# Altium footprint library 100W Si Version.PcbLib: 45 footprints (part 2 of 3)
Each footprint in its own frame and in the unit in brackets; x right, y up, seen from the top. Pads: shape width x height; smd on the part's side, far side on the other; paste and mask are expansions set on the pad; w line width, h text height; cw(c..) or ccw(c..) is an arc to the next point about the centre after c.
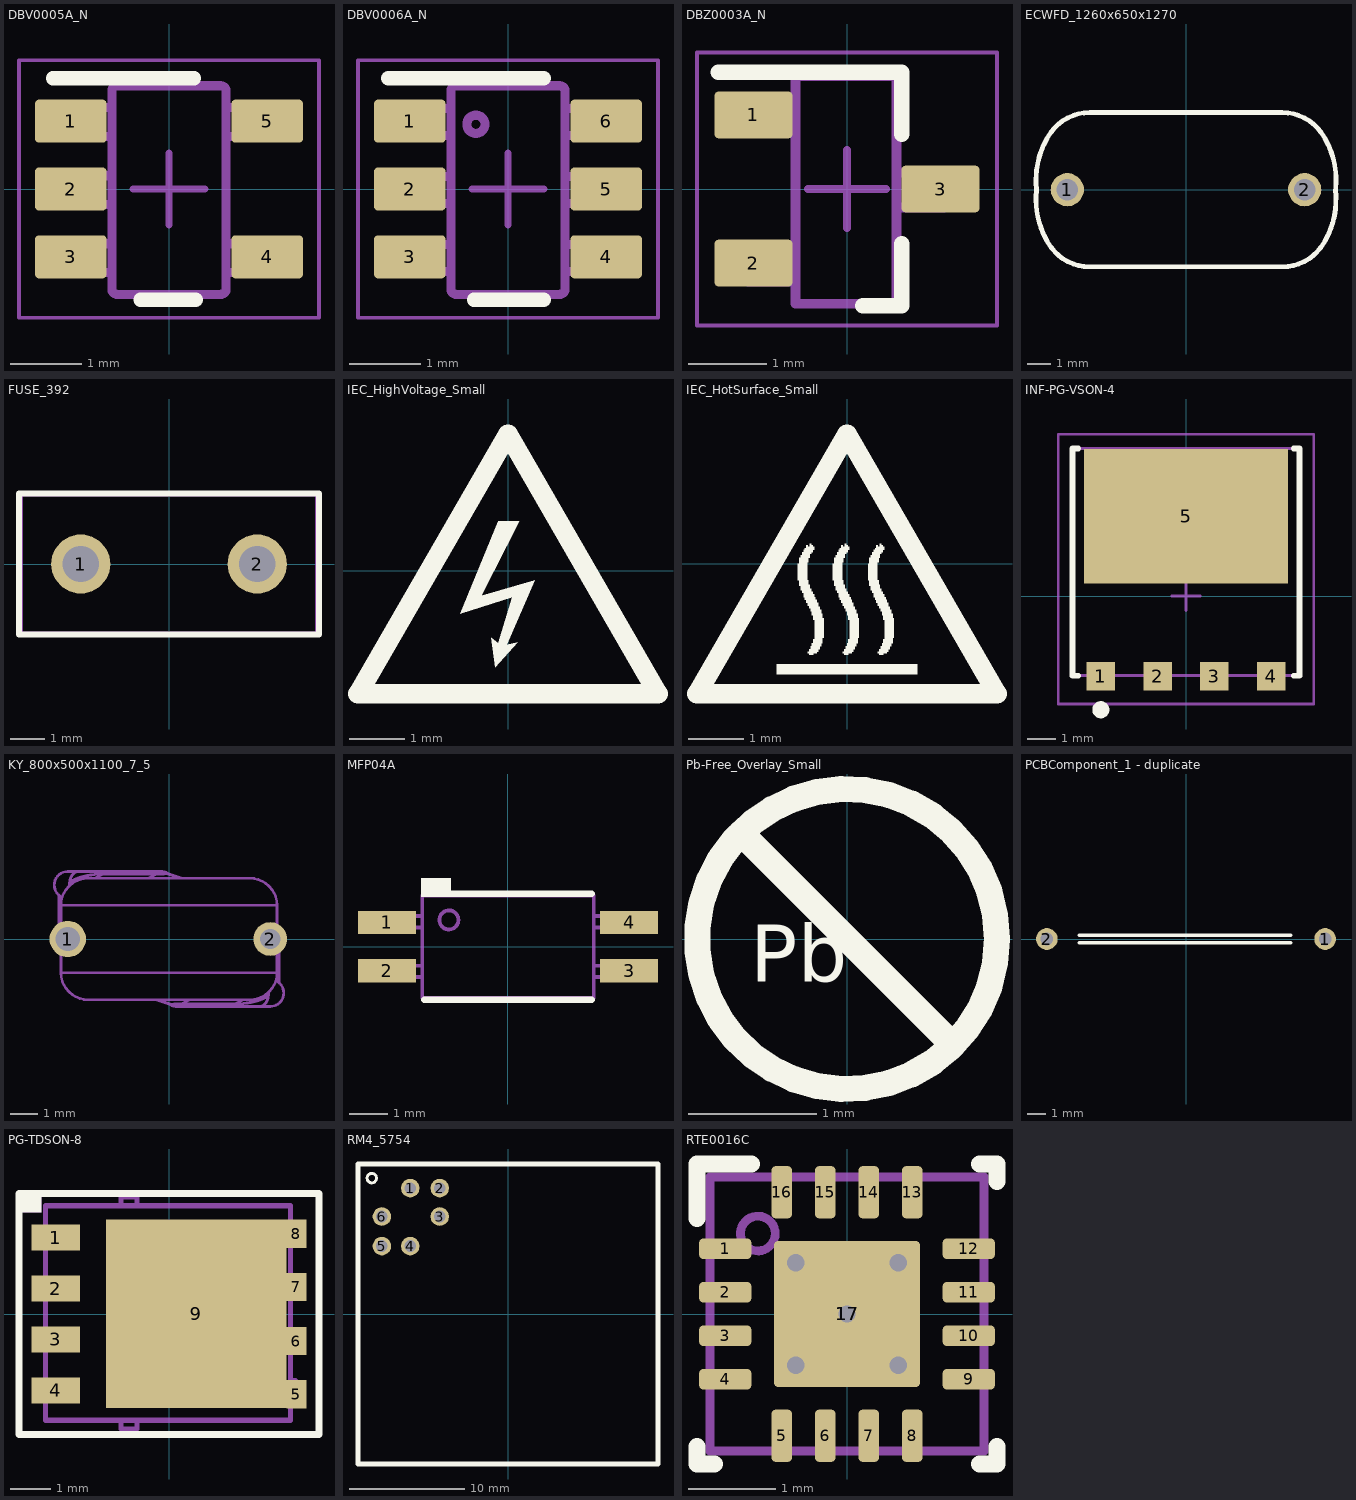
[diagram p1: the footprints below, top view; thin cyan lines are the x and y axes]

## DBV0005A_N [mm] "SOT23, 5-Leads, Body 2.9x1.6mm, Pitch 0.95mm, Lead Span 2.8mm, IPC Medium Density"
height 1.45
pads (5):
  rrect17% 1x0.6 smd: 1(-1.375,0.95) 2(-1.375,0) 3(-1.375,-0.95) 4(1.375,-0.95) 5(1.375,0.95)
Top Overlay:
  lines w0.2: -1.625,1.55 0.35,1.55 ; -0.4,-1.55 0.375,-1.55
Mechanical 5:
  lines w0.127: -0.801,1.371 cw(c-0.725,1.37) -0.725,1.446 ; -0.801,1.37 -0.801,1.371 ; -0.801,1.37 -0.801,-1.399 -0.801,-1.4 ccw(c-0.725,-1.399) -0.725,-1.475 ; -0.725,-1.475 0.723,-1.475 0.724,-1.475 ccw(c0.723,-1.399) 0.799,-1.4 0.799,-1.399 0.799,1.37 ; -0.725,-1.475 -0.725,-1.475 ; -0.725,1.446 -0.725,1.446 ; -0.725,1.446 0.723,1.446 0.724,1.446 cw(c0.723,1.37) 0.799,1.371 ; 0.799,1.37 0.799,1.371 ; -1.423,-1.167 -1.423,-0.767 -1.199,-0.767 -1.105,-0.767 -1.088,-0.767 -0.835,-0.767 -0.801,-0.767 -0.801,-1.167 -0.835,-1.167 -1.088,-1.167 -1.105,-1.167 -1.199,-1.167 -1.423,-1.167 ; -1.423,-0.215 -1.423,0.186 -1.199,0.186 -1.105,0.186 -1.088,0.186 -0.835,0.186 -0.801,0.186 -0.801,-0.215 -0.835,-0.215 -1.088,-0.215 -1.105,-0.215 -1.199,-0.215 -1.423,-0.215 ; -1.423,0.738 -1.423,1.138 -1.199,1.138 -1.105,1.138 -1.088,1.138 -0.835,1.138 -0.801,1.138 -0.801,0.738 -0.835,0.738 -1.088,0.738 -1.105,0.738 -1.199,0.738 -1.423,0.738 ; 0.799,-1.167 0.834,-1.167 1.087,-1.167 1.103,-1.167 1.198,-1.167 1.422,-1.167 1.422,-0.767 1.198,-0.767 1.103,-0.767 1.087,-0.767 0.834,-0.767 0.799,-0.767 0.799,-1.167 ; 0.799,0.738 0.834,0.738 1.087,0.738 1.103,0.738 1.198,0.738 1.422,0.738 1.422,1.138 1.198,1.138 1.103,1.138 1.087,1.138 0.834,1.138 0.799,1.138 0.799,0.738
Mechanical 15:
  lines w0.05: -2.1,-1.8 -2.1,1.8 2.1,1.8 2.1,-1.8 -2.1,-1.8
  lines w0.1: -0.5,0 0.5,0 ; 0,-0.5 0,0.5
3D body "DBV0005A.stp": height 1.09, standoff 0, extent -1.422,-1.46 1.422,1.461

## DBV0006A_N [mm] "SOT23, 6-Leads, Body 2.9x1.6mm, Pitch 0.95mm, Lead Span 2.8mm, IPC Medium Density"
height 1.45
pads (6):
  rrect17% 1x0.6 smd: 1(-1.375,0.95) 2(-1.375,0) 3(-1.375,-0.95) 4(1.375,-0.95) 5(1.375,0) 6(1.375,0.95)
Top Overlay:
  lines w0.2: -1.675,1.55 0.5,1.55 ; -0.475,-1.55 0.5,-1.55
Mechanical 5:
  lines w0.127: 0.724,-1.475 ccw(c0.723,-1.399) 0.8,-1.399 0.8,1.37 ccw(c0.723,1.37) 0.724,1.446 ; 0.723,-1.475 0.724,-1.475 ; 0.723,-1.475 -0.724,-1.475 -0.725,-1.475 cw(c-0.724,-1.399) -0.801,-1.399 -0.801,1.37 cw(c-0.724,1.37) -0.725,1.446 -0.724,1.446 0.723,1.446 ; 0.723,1.446 0.724,1.446 ; -1.423,-1.154 -1.206,-1.154 -1.113,-1.154 -1.081,-1.154 -0.828,-1.154 -0.801,-1.154 -0.801,-0.78 -0.828,-0.78 -1.081,-0.78 -1.113,-0.78 -1.206,-0.78 -1.423,-0.78 -1.423,-1.154 ; -1.423,-0.202 -1.206,-0.202 -1.113,-0.202 -1.081,-0.202 -0.828,-0.202 -0.801,-0.202 -0.801,0.173 -0.828,0.173 -1.081,0.173 -1.113,0.173 -1.206,0.173 -1.423,0.173 -1.423,-0.202 ; -1.423,0.751 -1.206,0.751 -1.113,0.751 -1.081,0.751 -0.828,0.751 -0.801,0.751 -0.801,1.125 -0.828,1.125 -1.081,1.125 -1.113,1.125 -1.206,1.125 -1.423,1.125 -1.423,0.751 ; -0.577,0.906 cw(c-0.45,0.906) -0.323,0.906 cw(c-0.45,0.906) -0.577,0.906 ; 0.8,-1.154 0.827,-1.154 1.08,-1.154 1.112,-1.154 1.205,-1.154 1.422,-1.154 1.422,-0.78 1.205,-0.78 1.112,-0.78 1.08,-0.78 0.827,-0.78 0.8,-0.78 0.8,-1.154 ; 0.8,-0.202 0.827,-0.202 1.08,-0.202 1.112,-0.202 1.205,-0.202 1.422,-0.202 1.422,0.173 1.205,0.173 1.112,0.173 1.08,0.173 0.827,0.173 0.8,0.173 0.8,-0.202 ; 0.8,0.751 0.827,0.751 1.08,0.751 1.112,0.751 1.205,0.751 1.422,0.751 1.422,1.125 1.205,1.125 1.112,1.125 1.08,1.125 0.827,1.125 0.8,1.125 0.8,0.751
  text ".Designator" at -0.075,0.925 h0.76
Mechanical 15:
  lines w0.05: -2.1,-1.8 2.1,-1.8 2.1,1.8 -2.1,1.8 -2.1,-1.8
  lines w0.1: -0.5,0 0.5,0 ; 0,-0.5 0,0.5
3D body "DBV0006A.stp": height 1.12, standoff 0, extent -1.422,-1.46 1.423,1.461

## DBZ0003A_N [mm] "SOT23, 3-Leads, Body 2.9x1.3mm, Pitch 0.95mm, Lead Span 2.4mm, IPC Medium Density"
height 1.12
pads (3):
  rrect17% 1x0.6 smd: 1(-1.2,0.95) 2(-1.2,-0.95) 3(1.2,0)
Top Overlay:
  lines w0.2: -1.651,1.5 0.7,1.5 0.7,0.7 ; 0.2,-1.5 0.7,-1.5 0.7,-0.7
Mechanical 5:
  lines w0.127: -1.27,-1.187 -1.27,-0.743 -1.063,-0.743 -1.005,-0.743 -0.814,-0.743 -0.66,-0.743 -0.66,-1.187 -0.814,-1.187 -1.005,-1.187 -1.063,-1.187 -1.27,-1.187 ; -1.27,0.718 -1.27,1.162 -1.063,1.162 -1.005,1.162 -0.814,1.162 -0.66,1.162 -0.66,0.718 -0.814,0.718 -1.005,0.718 -1.063,0.718 -1.27,0.718 ; -0.66,-1.473 -0.66,1.448 0.635,1.448 0.635,-1.473 -0.66,-1.473 ; 0.635,-0.235 0.789,-0.235 0.98,-0.235 1.037,-0.235 1.245,-0.235 1.245,0.21 1.037,0.21 0.98,0.21 0.789,0.21 0.635,0.21 0.635,-0.235
  text ".Designator" at -0.254,0.889 h0.76
Mechanical 15:
  lines w0.05: -1.925,-1.75 1.925,-1.75 1.925,1.75 -1.925,1.75 -1.925,-1.75
  lines w0.1: -0.5,0 0.5,0 ; 0,-0.5 0,0.5
3D body "DBZ0003A.stp": height 0.98, standoff 0, extent -1.257,-1.46 1.257,1.461

## ECWFD_1260x650x1270 [mm] "TH, 2-Leads, Body 12.6x6.5mm"
height 12.7
pads (2):
  round 1.4 hole 0.9: 1(-5,0) 2(5,0)
Top Overlay:
  lines w0.2: -6.1,-1.625 ccw(c-3.163,-0.595) -5.683,-2.422 -5.681,-2.424 ccw(c-4.058,-1.241) -4.057,-3.25 4.057,-3.25 ccw(c4.058,-1.241) 5.681,-2.424 5.683,-2.422 ccw(c3.163,-0.595) 6.1,-1.625 6.104,-1.614 ccw(c3.053,-0.466) 6.273,-0.975 ccw(c2.734,-0.412) 6.312,-0.609 6.317,-0.282 6.3,0 6.303,0.035 6.318,0.358 ccw(c2.479,0.392) 6.303,0.731 ccw(c2.99,0.448) 6.107,1.606 6.106,1.608 6.106,1.609 6.105,1.611 6.105,1.613 6.104,1.614 6.104,1.616 6.103,1.617 6.102,1.619 6.102,1.62 6.101,1.622 6.1,1.625 ; -6.1,-1.625 -6.101,-1.622 -6.102,-1.62 -6.102,-1.619 -6.103,-1.617 -6.104,-1.616 -6.105,-1.613 -6.106,-1.609 cw(c-2.968,-0.442) -6.309,-0.657 cw(c-2.406,-0.39) -6.317,-0.305 -6.3,0 -6.317,0.29 cw(c-2.345,0.389) -6.312,0.617 cw(c-2.746,0.413) -6.27,0.991 cw(c-3.059,0.468) -6.1,1.625 cw(c-3.163,0.595) -5.683,2.422 -5.681,2.424 cw(c-4.058,1.241) -4.057,3.25 4.057,3.25 cw(c4.058,1.241) 5.681,2.424 5.683,2.422 cw(c3.163,0.595) 6.1,1.625
Mechanical 5:
  lines w0.1: -6.1,-1.625 ccw(c-3.163,-0.595) -5.683,-2.422 -5.681,-2.424 ccw(c-4.058,-1.241) -4.057,-3.25 4.057,-3.25 ccw(c4.058,-1.241) 5.681,-2.424 5.683,-2.422 ccw(c3.163,-0.595) 6.1,-1.625 6.104,-1.614 ccw(c3.053,-0.466) 6.273,-0.975 ccw(c2.734,-0.412) 6.312,-0.609 6.317,-0.282 6.3,0 6.303,0.035 6.318,0.358 ccw(c2.479,0.392) 6.303,0.731 ccw(c2.99,0.448) 6.107,1.606 6.106,1.608 6.106,1.609 6.105,1.611 6.105,1.613 6.104,1.614 6.104,1.616 6.103,1.617 6.102,1.619 6.102,1.62 6.101,1.622 6.1,1.625 ; -6.1,-1.625 -6.101,-1.622 -6.102,-1.62 -6.102,-1.619 -6.103,-1.617 -6.104,-1.616 -6.105,-1.613 -6.106,-1.609 cw(c-2.968,-0.442) -6.309,-0.657 cw(c-2.406,-0.39) -6.317,-0.305 -6.3,0 -6.317,0.29 cw(c-2.345,0.389) -6.312,0.617 cw(c-2.746,0.413) -6.27,0.991 cw(c-3.059,0.468) -6.1,1.625 cw(c-3.163,0.595) -5.683,2.422 -5.681,2.424 cw(c-4.058,1.241) -4.057,3.25 4.057,3.25 cw(c4.058,1.241) 5.681,2.424 5.683,2.422 cw(c3.163,0.595) 6.1,1.625
  text ".Designator" at -2.8,-1 h1.02
3D body "ECWFD_1260x650x1270.stp": height 12.71, standoff -4, extent -6.312,-3.25 6.313,3.25

## FCC_disclaimer [mm]

## FUSE_392 [mm] "LITTELFUSE"
height 8
pads (2):
  round 1.7 hole 1.05: 1(-2.54,0) 2(2.54,0)
Top Overlay:
  lines w0.17: -4.318,-2.032 -4.318,2.032 4.318,2.032 4.318,-2.032 -4.318,-2.032
Mechanical 5:
  lines w0.1: -4.25,-2 -4.25,2 4.25,2 4.25,-2 -4.25,-2
  text ".Designator" at -1.778,-0.508 h1.02
3D body: height 1, standoff -2, extent -2.838,-0.299 -2.24,0.299
3D body: height 1, standoff -2, extent 2.242,-0.299 2.84,0.3
3D body: height 8, standoff 0, extent -4.249,-1.999 4.249,1.999

## IEC_HighVoltage_Small [mm]
Top Overlay:
  region: -0.178,0.889 0.203,0.889 -0.483,-0.457 0.483,-0.178 -0.025,-1.346 0.178,-1.295 -0.229,-1.753 -0.305,-1.219 -0.178,-1.321 0.076,-0.483 -0.864,-0.787
  lines w0.356: -2.718,-2.235 0,2.472 2.718,-2.235 -2.718,-2.235

## IEC_HotSurface_Small [mm]
Top Overlay:
  drawing of 10 lines, arcs and shapes, not listed

## INF-PG-VSON-4 [mm] "VSON,2.00mm pitch,8.00mm W X 8.00mm L X 1.1mm H body"
height 1.1
pads (5):
  rect 1x1 smd paste+0 mask+0: 1(-3,-2.815) 2(-1,-2.815) 3(1,-2.815) 4(3,-2.815)
  rect 7.2x4.75 smd paste+0 mask+0: 5(0,2.815)
Top Overlay:
  circle w0.3: c-3,-4 r0.15
  lines w0.2: -3.8,-2.8 -4,-2.8 -4,5.2 -3.8,5.2 ; 3.8,-2.8 4,-2.8 4,5.2 3.8,5.2
Mechanical 3:
  text ".DESIGNATOR" at 0,0 h1.2
Mechanical 13:
  lines w0.1: -4,-2.8 4,-2.8 4,5.2 -4,5.2 -4,-2.8
Mechanical 15:
  lines w0.1: -0.5,0 0.5,0 ; 0,-0.5 0,0.5 ; -4.5,-3.8 4.5,-3.8 4.5,5.7 -4.5,5.7 -4.5,-3.8
3D body "PG-VSON-4-1_C66065-A0003-C769-02-0004.stp": height 1.01, standoff 0, extent -4,-2.8 4,5.2

## KY_800x500x1100_7_5 [mm] "TH, 2-Leads, Body 8x5mm, Pin Spacing 7.5mm"
height 11
pads (2):
  round 1.35 hole 0.9: 1(-3.75,0)
  round 1.25 hole 0.75: 2(3.75,0)
Mechanical 5:
  drawing of 3200 lines, arcs and shapes, not listed
  text ".Designator" at -1.651,-0.381 h0.9
3D body "KY_800x500.stp": height 11, standoff -3, extent -4.25,-2.5 4.25,2.5

## MFP04A [mm] "FAIRCHILD optocoupler"
height 2.39
pads (4):
  rect 1.52x0.61 smd: 1(-3.175,0.635) 2(-3.175,-0.635) 3(3.175,-0.635) 4(3.175,0.635)
Top Overlay:
  rectangle: -2.28,1.3 -1.5,1.8
  lines w0.17: -2.2,-1.4 2.2,-1.4 ; -2.2,1.385 2.2,1.385
Mechanical 5:
  circle w0.1: c-1.55,0.7 r0.25
  lines w0.1: -2.25,-0.8 -3.6,-0.8 -3.6,-0.5 -2.25,-0.5 ; -2.25,0.5 -3.6,0.5 -3.6,0.8 -2.25,0.8 ; 2.25,-0.8 3.6,-0.8 3.6,-0.5 2.25,-0.5 ; 2.25,0.5 3.6,0.5 3.6,0.8 2.25,0.8 ; -2.25,-1.345 -2.25,1.345 2.25,1.345 2.25,-1.345 -2.25,-1.345
3D body: height 1.2, standoff 0, extent 2.251,0.501 3.599,0.799
3D body: height 1.2, standoff 0, extent 2.251,-0.799 3.599,-0.501
3D body: height 1.2, standoff 0, extent -3.599,0.501 -2.251,0.799
3D body: height 1.2, standoff 0, extent -3.599,-0.799 -2.251,-0.501
3D body: height 2.39, standoff 0, extent -2.249,-1.344 2.249,1.344
3D body: height 2.39, standoff 2, extent -1.799,0.451 -1.301,0.949

## Pb-Free_Overlay_Small [mm]
height 47
Top Overlay:
  circle w0.203: c0,0 r1.168
  lines w0.203: -0.826,0.826 0.826,-0.826
  text "Pb" at -0.752,-0.48 h0.76

## PCBComponent_1 - duplicate [mm]
pads (2):
  round 1.2 hole 0.7: 1(7.7,0) 2(-7.7,0)
Top Overlay:
  lines w0.2: -5.9,-0.2 5.8,-0.2 ; -5.9,0.2 5.8,0.2
Mechanical 5:
  text ".Designator" at -2,-0.7 h1.85

## PG-TDSON-8 [mm] "Infineon recommended land pattern"
height 1.1
pads (9):
  rect 1.2x0.65 smd: 1(-2.825,1.905) 2(-2.825,0.635) 3(-2.825,-0.635) 4(-2.825,-1.905)
  rect 0.5x0.7 smd: 5(3.175,-2) 6(3.175,-0.675) 7(3.175,0.675) 8(3.175,2)
  rect 4.5x4.7 smd paste-2.25: 9(0.675,0)
Top Overlay:
  rectangle: -3.74,2.527 -3.175,2.975
  lines w0.178: -3.74,-3 -0.105,-3 3.74,-3 3.74,0 3.74,3 0.105,3 -3.74,3 -3.74,0 -3.74,-3
Top Paste:
  rectangle: -1.475,-2.25 -0.242,-0.95
  rectangle: 0.058,-2.25 1.291,-0.95
  rectangle: 1.591,-2.25 2.824,-0.95
  rectangle: 1.591,-0.65 2.824,0.65
  rectangle: 0.058,-0.65 1.291,0.65
  rectangle: -1.475,-0.65 -0.242,0.65
  rectangle: 1.591,0.95 2.824,2.25
  rectangle: 0.058,0.95 1.291,2.25
  rectangle: -1.475,0.95 -0.242,2.25
Mechanical 5:
  rectangle: -3.74,2.527 -3.175,2.975
  lines w0.127: -3.075,-2.1 -3.2,-2.1 -3.2,-1.66 -3.075,-1.66 ; -3.075,-0.83 -3.2,-0.83 -3.2,-0.39 -3.075,-0.39 ; -3.075,0.44 -3.2,0.44 -3.2,0.88 -3.075,0.88 ; -3.075,1.71 -3.2,1.71 -3.2,2.15 -3.075,2.15 ; -1.2,-2.65 -1.2,-2.87 -0.8,-2.87 -0.8,-2.65 ; -1.2,2.7 -1.2,2.92 -0.8,2.92 -0.8,2.7 ; 3.025,-2.1 3.15,-2.1 3.15,-1.66 3.025,-1.66 ; 3.025,-0.83 3.15,-0.83 3.15,-0.39 3.025,-0.39 ; 3.025,0.44 3.15,0.44 3.15,0.88 3.025,0.88 ; 3.025,1.71 3.15,1.71 3.15,2.15 3.025,2.15 ; -3.075,-2.65 -3.075,2.7 3.025,2.7 3.025,-2.65 -3.075,-2.65
3D body "PG-TDSON-8.stp": height 1.1, standoff 0, extent -3.175,-2.895 3.175,2.895

## RM4_5754 [mm] "THT, Body 11.44x11.44mm, 6Pin, Pitch 2.54mm"
height 11.18
pads (6):
  round 1.62 hole 1.02: 1(-8.525,10.975) 2(-5.95,10.975) 3(-5.95,8.5) 4(-8.525,5.925) 5(-11,5.925) 6(-11,8.5)
Top Overlay:
  circle w0.254: c-11.875,11.85 r0.412
  lines w0.4: -13.08,-13.08 -13.08,13.08 13.08,13.08 13.08,-13.08 -13.08,-13.08

## RTE0016C [mm] "Texas Insturments"
height 0.8
pads (18):
  rrect42% 0.6x0.24 smd: 1(-1.4,0.75) 2(-1.4,0.25) 3(-1.4,-0.25) 4(-1.4,-0.75) 9(1.4,-0.75) 10(1.4,-0.25) 11(1.4,0.25) 12(1.4,0.75)
  rrect42% 0.24x0.6 smd: 5(-0.75,-1.4) 6(-0.25,-1.4) 7(0.25,-1.4) 8(0.75,-1.4) 13(0.75,1.4) 14(0.25,1.4) 15(-0.25,1.4) 16(-0.75,1.4)
  rrect50% 1.55x1.55 on Top Paste: 17(0,0)
  rrect6% 1.68x1.68 smd paste-0.85: 17(0,0)
via 0.59,0.59 diameter 0.5 hole 0.2
via -0.59,0.59 diameter 0.5 hole 0.2
via 0.59,-0.59 diameter 0.5 hole 0.2
via 0,0 diameter 0.5 hole 0.2
via -0.59,-0.59 diameter 0.5 hole 0.2
Top Overlay:
  lines w0.2: -1.725,-1.525 -1.725,-1.725 -1.525,-1.725 ; -1.725,1.1 -1.725,1.725 -1.1,1.725 ; 1.525,-1.725 1.725,-1.725 1.725,-1.525 ; 1.525,1.725 1.725,1.725 1.725,1.525
Mechanical 5:
  circle w0.1: c-1.025,0.925 r0.2
  lines w0.1: -1.575,-1.575 -1.575,1.575 1.575,1.575 1.575,-1.575 -1.575,-1.575
  text ".Designator" at -3.91,-0.609 h0.76
3D body "RTE0016C.stp": height 0.8, standoff 0, extent -1.5,-1.5 1.5,1.5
